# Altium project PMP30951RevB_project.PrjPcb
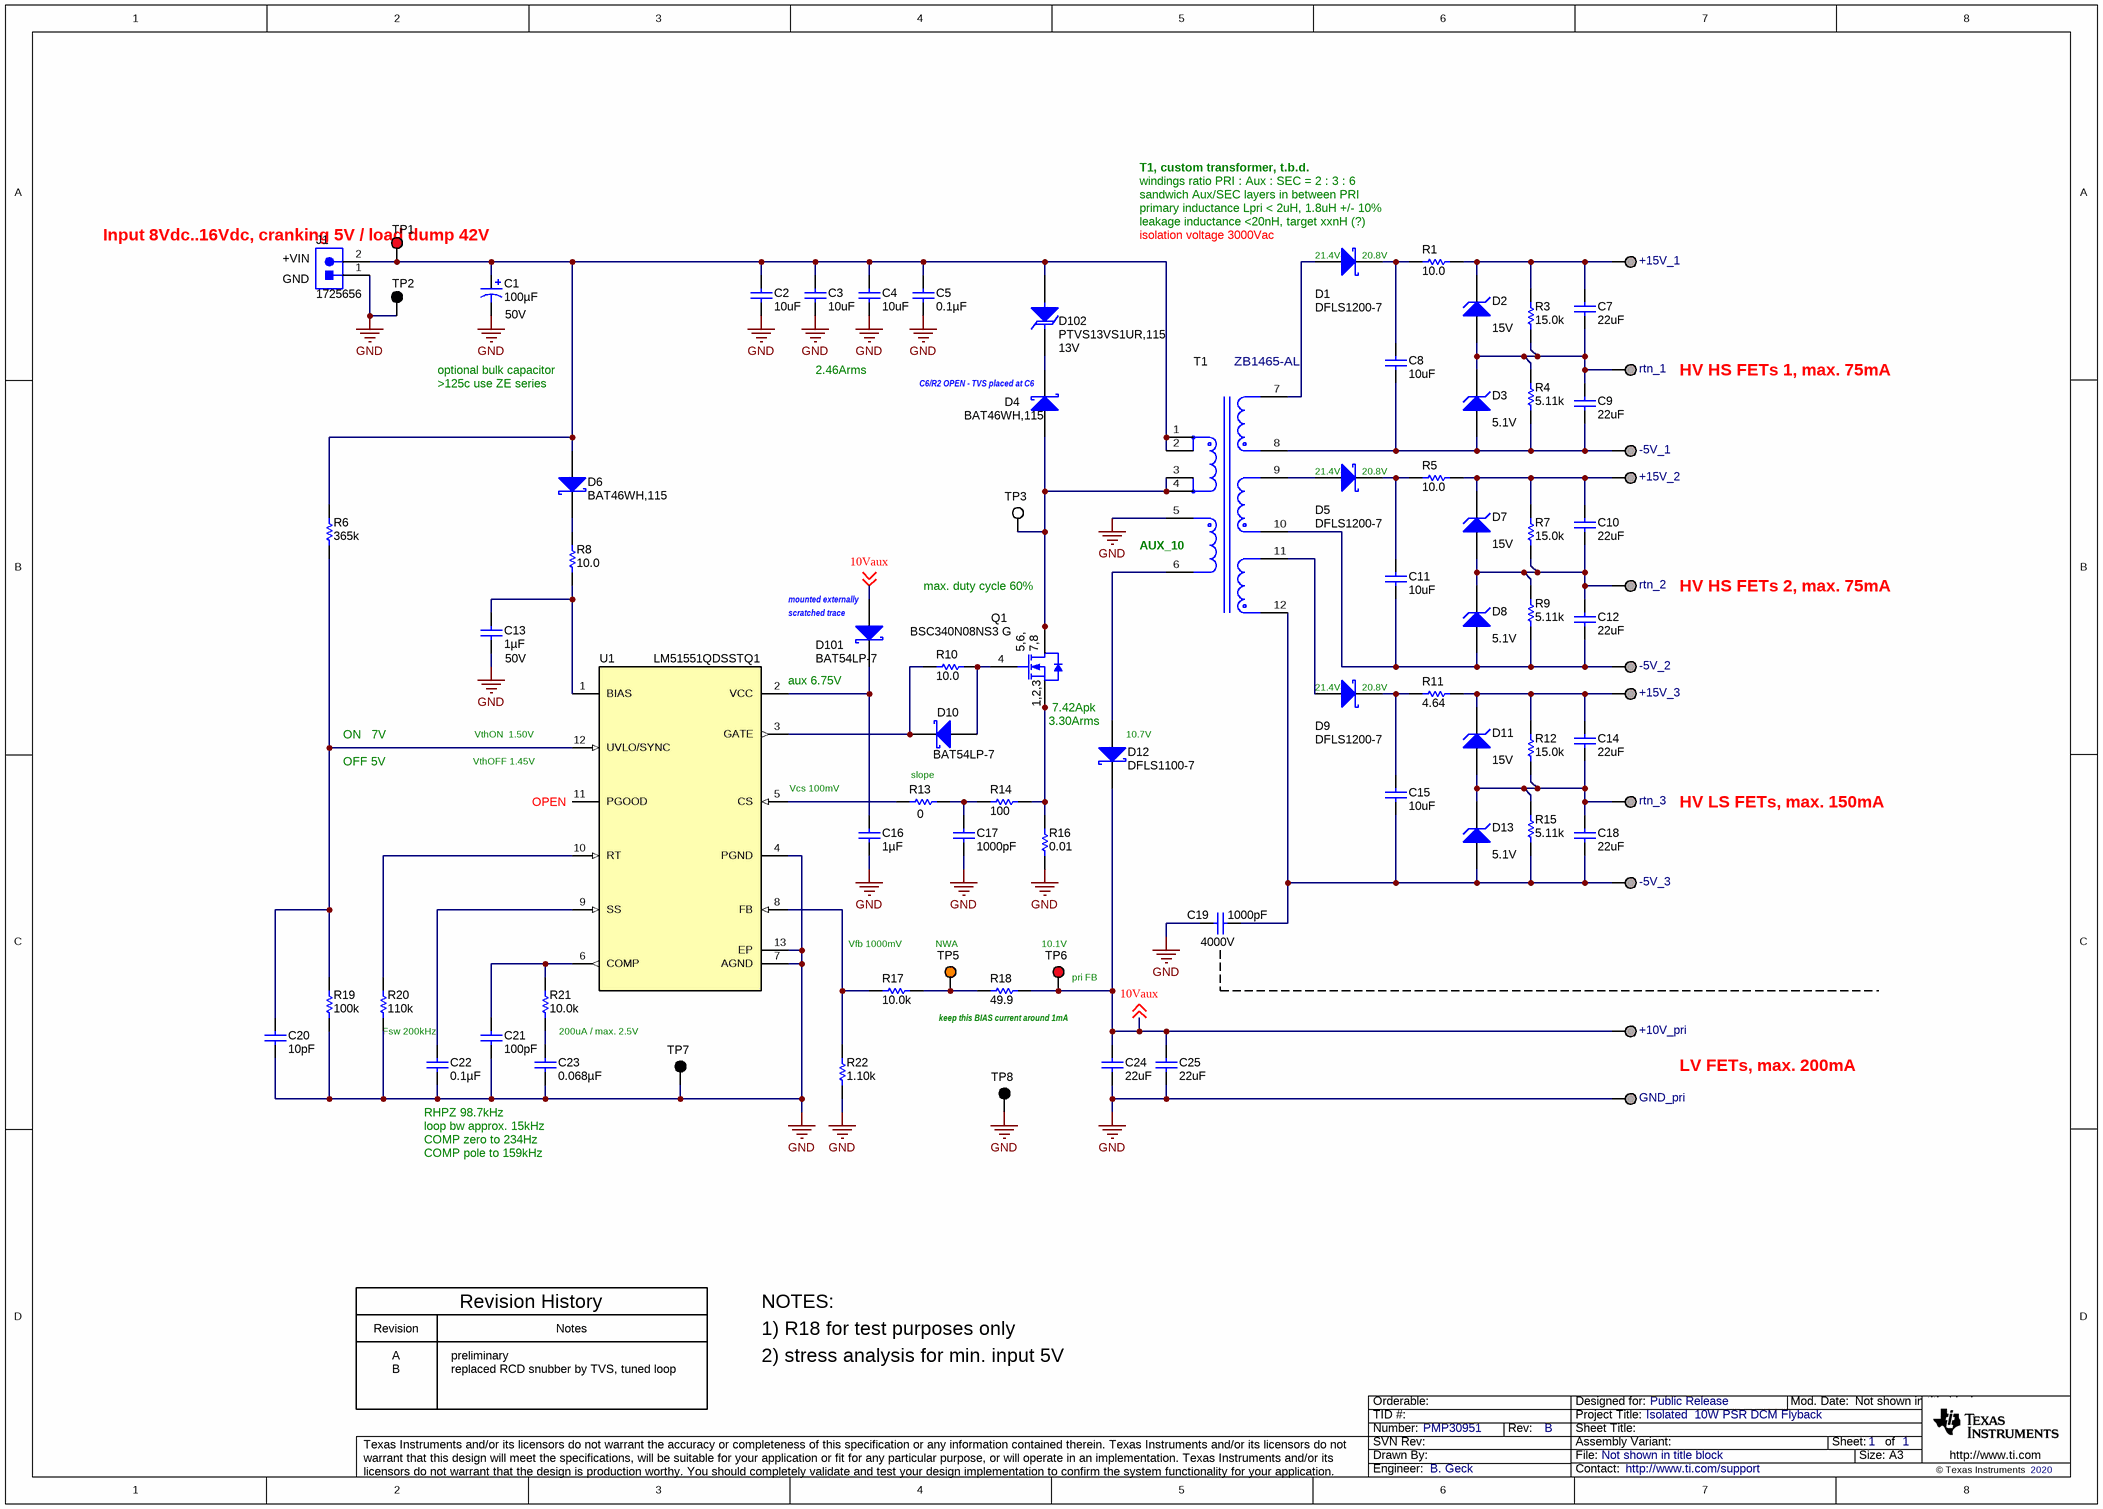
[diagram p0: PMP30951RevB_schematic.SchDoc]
TechSupport: http://www.ti.com/support; SCH_Rev: B; PRJ_Title: Isolated  10W PSR DCM Flyback; PRJ_Number: PMP30951; PRJ_Engineer: B. Geck; PRJ_Customer: Public Release; PCB_Rev: A1; PCB_Layout: B. Geck; CopyrightYear: 2020
1 sheet, 82 parts. Net scope: global (net labels, ports and power ports of the same name join across sheets).
Board file: PMP30951RevA1_board.PcbDoc

## Sheet PMP30951RevB_schematic.SchDoc
size A3; Date: Not shown in title block; ApprovedBy: Not shown in title block; CheckedBy: Not shown in title block; Author: Not shown in title block; CompanyName: Not shown in title block; Engineer: Not shown in title block; Organization: Not shown in title block; Address1: Not shown in title block; Address2: Not shown in title block; Address3: Not shown in title block; Address4: Not shown in title block; DocumentNumber: 1; Revision: Use project parameter SCH_Rev; SheetNumber: 1; SheetTotal: 1; PageSetup: Record=PageOptions¦CenterHorizontal=True¦CenterVertical=True¦PrintScale=0.68¦XCorrection=1.00¦YCorrection=1.00¦PrintKind=0¦BorderSize=5000000¦LeftOffset=0¦BottomOffset=0¦Orientation=2¦PaperLength=1000¦PaperWidth=1000¦Scale=100¦PaperSource=15¦PrintQuality=600¦MediaType=1¦DitherType=10¦PrintScaleMode=1¦PaperKind=A4¦PaperIndex=9

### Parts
+10V_pri  Suggest using a net name here  [Keystone1503-2]  (value not drawn)
+15V_1  Suggest using a net name here  [Keystone1503-2]  (value not drawn)
+15V_2  Suggest using a net name here  [Keystone1503-2]  (value not drawn)
+15V_3  Suggest using a net name here  [Keystone1503-2]  (value not drawn)
-5V_1  Suggest using a net name here  [Keystone1503-2]  (value not drawn)
-5V_2  Suggest using a net name here  [Keystone1503-2]  (value not drawn)
-5V_3  Suggest using a net name here  [Keystone1503-2]  (value not drawn)
C1  ValueDisplayed: 100µF  Value2: 50V  [Panasonic_G]  (hidden comment: EEH-ZC1H101P)
C2  ValueDisplayed: 10uF  [1210_270]  (hidden comment: GRM32ER71H106KA12L)
C3  ValueDisplayed: 10uF  [1210_270]  (hidden comment: GRM32ER71H106KA12L)
C4  ValueDisplayed: 10uF  [1210_270]  (hidden comment: GRM32ER71H106KA12L)
C5  ValueDisplayed: 0.1µF  [0603]  (hidden comment: GCM188R71H104KA57D)
C7  ValueDisplayed: 22uF  [1210_270]  (hidden comment: GRM32ER71E226KE15L)
C8  ValueDisplayed: 10uF  [1210_270]  (hidden comment: GRM32ER71H106KA12L)
C9  ValueDisplayed: 22uF  [1210_270]  (hidden comment: GRM32ER71E226KE15L)
C10  ValueDisplayed: 22uF  [1210_270]  (hidden comment: GRM32ER71E226KE15L)
C11  ValueDisplayed: 10uF  [1210_270]  (hidden comment: GRM32ER71H106KA12L)
C12  ValueDisplayed: 22uF  [1210_270]  (hidden comment: GRM32ER71E226KE15L)
C13  ValueDisplayed: 1µF  Value2: 50V  [0805_HV]  (hidden comment: GRM21BR71H105KA12L)
C14  ValueDisplayed: 22uF  [1210_270]  (hidden comment: GRM32ER71E226KE15L)
C15  ValueDisplayed: 10uF  [1210_270]  (hidden comment: GRM32ER71H106KA12L)
C16  ValueDisplayed: 1µF  [0603]  (hidden comment: GRM188R71C105KA12D)
C17  ValueDisplayed: 1000pF  [0603]  (hidden comment: GRM188R71E102KA01D)
C18  ValueDisplayed: 22uF  [1210_270]  (hidden comment: GRM32ER71E226KE15L)
C19  ValueDisplayed: 1000pF  Value2: 4000V  [1812_280]  (hidden comment: HV1812Y102KXVATHV)
C20  ValueDisplayed: 10pF  [0603]  (hidden comment: GRM1885C1H100JA01D)
C21  ValueDisplayed: 100pF  [0603]  (hidden comment: GRM1885C1H101JA01D)
C22  ValueDisplayed: 0.1µF  [0603]  (hidden comment: GRM188R71E104KA01D)
C23  ValueDisplayed: 0.068µF  [0603]  (hidden comment: GRM188R71E683KA01D)
C24  ValueDisplayed: 22uF  [1210_270]  (hidden comment: GRM32ER71E226KE15L)
C25  ValueDisplayed: 22uF  [1210_270]  (hidden comment: GRM32ER71E226KE15L)
D1  DFLS1200-7  [PowerDI123]
D2  value 15V  [SOD-123]  (hidden comment: MMSZ5245B-7-F)
D3  value 5.1V  [SOD-123]  (hidden comment: MMSZ5231B-7-F)
D4  BAT46WH,115  [SOD-123F]
D5  DFLS1200-7  [PowerDI123]
D6  BAT46WH,115  [SOD-123F]
D7  value 15V  [SOD-123]  (hidden comment: MMSZ5245B-7-F)
D8  value 5.1V  [SOD-123]  (hidden comment: MMSZ5231B-7-F)
D9  DFLS1200-7  [PowerDI123]
D10  BAT54LP-7  [X1-DFN1006-2]
D11  value 15V  [SOD-123]  (hidden comment: MMSZ5245B-7-F)
D12  DFLS1100-7  [PowerDI123]
D13  value 5.1V  [SOD-123]  (hidden comment: MMSZ5231B-7-F)
D101  BAT54LP-7  [X1-DFN1006-2]
D102  PTVS13VS1UR,115  value 13V  [SOD-123W]
GND_pri  Suggest using a net name here  [Keystone1503-2]  (value not drawn)
J1  1725656  [CONN_1725656]
Q1  BSC340N08NS3 G  [PG-TDSON-8]
R1  ValueDisplayed: 10.0  [0805_HV]  (hidden comment: CRCW080510R0FKEA)
R3  ValueDisplayed: 15.0k  [0603]  (hidden comment: CRCW060315K0FKEA)
R4  ValueDisplayed: 5.11k  [0603]  (hidden comment: CRCW06035K11FKEA)
R5  ValueDisplayed: 10.0  [0805_HV]  (hidden comment: CRCW080510R0FKEA)
R6  ValueDisplayed: 365k  [0603]  (hidden comment: CRCW0603365KFKEA)
R7  ValueDisplayed: 15.0k  [0603]  (hidden comment: CRCW060315K0FKEA)
R8  ValueDisplayed: 10.0  [0603]  (hidden comment: CRCW060310R0FKEA)
R9  ValueDisplayed: 5.11k  [0603]  (hidden comment: CRCW06035K11FKEA)
R10  ValueDisplayed: 10.0  [0603]  (hidden comment: CRCW060310R0FKEA)
R11  ValueDisplayed: 4.64  [0805_HV]  (hidden comment: CRCW08054R64FKEA)
R12  ValueDisplayed: 15.0k  [0603]  (hidden comment: CRCW060315K0FKEA)
R13  ValueDisplayed: 0  [0603]  (hidden comment: CRCW06030000Z0EA)
R14  ValueDisplayed: 100  [0603]  (hidden comment: CRCW0603100RFKEA)
R15  ValueDisplayed: 5.11k  [0603]  (hidden comment: CRCW06035K11FKEA)
R16  ValueDisplayed: 0.01  [WSLHP0805]  (hidden comment: WSL0805R0100FEA18)
R17  ValueDisplayed: 10.0k  [0603]  (hidden comment: CRCW060310K0FKEA)
R18  ValueDisplayed: 49.9  [0603]  (hidden comment: CRCW060349R9FKEA)
R19  ValueDisplayed: 100k  [0603]  (hidden comment: CRCW0603100KFKEA)
R20  ValueDisplayed: 110k  [0603]  (hidden comment: CRCW0603110KFKEA)
R21  ValueDisplayed: 10.0k  [0603]  (hidden comment: CRCW060310K0FKEA)
R22  ValueDisplayed: 1.10k  [0603]  (hidden comment: CRCW06031K10FKEA)
rtn_1  Suggest using a net name here  [Keystone1503-2]  (value not drawn)
rtn_2  Suggest using a net name here  [Keystone1503-2]  (value not drawn)
rtn_3  Suggest using a net name here  [Keystone1503-2]  (value not drawn)
T1  ZB1465-AL  [FP-ZB1465-AL_SMT_XFRMR_21MM97_17MM20-MFG]
TP1  5010  [Keystone5010]  (value not drawn)
TP2  5011  [Keystone5011]  (value not drawn)
TP3  5002  [Keystone5002]  (value not drawn)
TP5  5003  [Keystone5003]  (value not drawn)
TP6  5000  [Keystone5000]  (value not drawn)
TP7  5001  [Keystone5001]  (value not drawn)
TP8  5001  [Keystone5001]  (value not drawn)
U1  LM51551QDSSTQ1  [DSS0012C]

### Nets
GND: C1.2(-) C2.2 C3.2 C4.2 C5.2 C13.2 C16.2 C17.2 C19.2 C20.2 C21.2 C22.2 C23.2 C24.2 C25.2 GND_pri.1 J1.1 R16.1 R19.1 R20.1 R22.1 T1.5 TP2.1 TP7.1 TP8.1 U1.4(PGND) U1.7(AGND) U1.13(EP)
10Vaux: +10V_pri.1 C24.1 C25.1 D12.1(K) D101.2(A) R18.2 TP6.1 ; off-sheet 10Vaux
Net+15V_1_1: +15V_1.1 C7.1 D2.1(K) R1.2 R3.2
Net+15V_2_1: +15V_2.1 C10.1 D7.1(K) R5.2 R7.2
Net+15V_3_1: +15V_3.1 C14.1 D11.1(K) R11.2 R12.2
Net-5V_1_1: -5V_1.1 C8.2 C9.2 D3.2(A) R4.1 T1.8
Net-5V_2_1: -5V_2.1 C11.2 C12.2 D8.2(A) R9.1 T1.10
Net-5V_3_1: -5V_3.1 C15.2 C18.2 C19.1 D13.2(A) R15.1 T1.12
NetC1_1: C1.1(+) C2.1 C3.1 C4.1 C5.1 D6.2(A) D102.2(A) J1.2 R6.2 T1.1 T1.2 TP1.1
NetC7_2: C7.2 C9.1 D2.2(A) D3.1(K) R3.1 R4.2 rtn_1.1
NetC8_1: C8.1 D1.1(K) R1.1
NetC10_2: C10.2 C12.1 D7.2(A) D8.1(K) R7.1 R9.2 rtn_2.1
NetC11_1: C11.1 D5.1(K) R5.1
NetC13_1: C13.1 R8.1 U1.1(BIAS)
NetC14_2: C14.2 C18.1 D11.2(A) D13.1(K) R12.1 R15.2 rtn_3.1
NetC15_1: C15.1 D9.1(K) R11.1
NetC16_1: C16.1 D101.1(K) U1.2(VCC)
NetC17_1: C17.1 R13.2 R14.1
NetC20_1: C20.1 R6.1 R19.2 U1.12(UVLO/SYNC)
NetC21_1: C21.1 R21.2 U1.6(COMP)
NetC22_1: C22.1 U1.9(SS)
NetC23_1: C23.1 R21.1
NetD1_2: D1.2(A) T1.7
NetD4_1: D4.1(K) D102.1(K)
NetD4_2: D4.2(A) Q1.5(D) Q1.6(D) Q1.7(D) Q1.8(D) Q1.9(D) T1.3 T1.4 TP3.1
NetD5_2: D5.2(A) T1.9
NetD6_1: D6.1(K) R8.2
NetD9_2: D9.2(A) T1.11
NetD10_1: D10.1(K) R10.1 U1.3(GATE)
NetD10_2: D10.2(A) Q1.4(G) R10.2
NetD12_2: D12.2(A) T1.6
NetQ1_1: Q1.1(S) Q1.2(S) Q1.3(S) R14.2 R16.2
NetR13_1: R13.1 U1.5(CS)
NetR17_1: R17.1 R22.2 U1.8(FB)
NetR17_2: R17.2 R18.1 TP5.1
NetR20_2: R20.2 U1.10(RT)

Not connected (* = marked no-connect by the designer): U1 11(PGOOD)

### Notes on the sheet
- windings ratio PRI : Aux : SEC = 2 : 3 : 6
- T1, custom transformer, t.b.d.
- Input 8Vdc..16Vdc, cranking 5V / load dump 42V
- primary inductance Lpri < 2uH, 1.8uH +/- 10%
- leakage inductance <20nH, target xxnH (?)
- sandwich Aux/SEC layers in between PRI
- isolation voltage 3000Vac
- (near J1) +VIN
- (near J1) GND
- (near D1) 21.4V
- (near D1) 20.8V
- optional bulk capacitor
- >125c use ZE series
- 2.46Arms
- (near D4) C6/R2 OPEN - TVS placed at C6
- HV HS FETs 1, max. 75mA
- (near D5) 21.4V
- (near D5) 20.8V
- max. duty cycle 60%
- (near T1) AUX_10
- HV HS FETs 2, max. 75mA
- (near D101) scratched trace
- (near D101) mounted externally
- aux 6.75V
- 3.30Arms
- (near Q1) 7.42Apk
- (near D9) 21.4V
- (near D9) 20.8V
- ON   7V
- OFF 5V
- VthON  1.50V
- VthOFF 1.45V
- Vcs 100mV
- slope
- (near D12) 10.7V
- (near U1) OPEN
- HV LS FETs, max. 150mA
- Vfb 1000mV
- (near TP5) NWA
- (near TP6) 10.1V
- (near TP6) pri FB
- (near R20) Fsw 200kHz
- 200uA / max. 2.5V
- keep this BIAS current around 1mA
- (near C22) RHPZ 98.7kHz
- loop bw approx. 15kHz
- LV FETs, max. 200mA
- COMP zero to 234Hz
- COMP pole to 159kHz
- Revision
- Revision History
- Notes
- NOTES:
- 1) R18 for test purposes only
- A
- B
- preliminary
- replaced RCD snubber by TVS, tuned loop
- 2) stress analysis for min. input 5V

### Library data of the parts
+10V_pri +15V_1-+15V_3 -5V_1--5V_3 GND_pri rtn_1-rtn_3 = 1503-2: Terminal, Turret, TH, Double; Manufacturer: Keystone; CompType: Turret Terminal; U/M: EA
C1 = EEH-ZC1H101P: CAP, Polymer Hybrid, 100 µF, 50 V,+/- 20%, 0.028 ohm, AEC-Q200 Grade 1, D10xL10.2mm SMD; Manufacturer: Panasonic; Polarized: Y; CompType: Capacitor; Value: 100uF; U/M: EA; Cap_F: 0.0001; Tolerance_%: 20; VDC_V: 50; ESR_ohm: 0.028; IRMS_A: 1.6; TaMin_C: -55; TaMax_C: 125; Cap_Case: 10x10.2mm; SizeAreaWB_mm2: 151.29; SizeArea_mm2: 106.09; SizeX_mm: 10.3; SizeZ_mm: 10.5; AEC Category: Q200; AEC Grade: 1
C2-C4 C8 C11 C15 = CMP-0009226-3: CAP, CERM, 10 uF, 50 V, +/- 10%, X7R, 1210; Manufacturer: MuRata; Polarized: N; Value: 10uF; U/M: EA; Cap_F: 10µF; Value1: Unknown; VDC_V: 50V; TaMin_C: -55°C; TaMax_C: 125°C; Cap_Case: 1210; AEC Category: Q200; SizeArea_mm2: 8; SizeAreaWB_mm2: 14.7; SizeX_mm: 3.2; SizeY_mm: 2.5; SizeZ_mm: 2.7
C5 = GCM188R71H104KA57D: CAP, CERM, 0.1 µF, 50 V, +/- 10%, X7R, 0603; Manufacturer: MuRata; Polarized: N; CompType: Capacitor; Value: 0.1uF; U/M: EA; Cap_F: 0.0000001; Tolerance_%: 10; ESR_ohm: 0.02; Value1: 0.02 ohm; VDC_V: 50; Value2: 50V; IRMS_A: 1.84; TaMin_C: -55; TaMax_C: 125; AEC Category: Q200
C7 C9 C10 C12 C14 C18 C24 C25 = CMP-0009224-2: CAP, CERM, 22 uF, 25 V, +/- 10%, X7R, 1210; Manufacturer: MuRata; Polarized: N; Value: 22uF; U/M: EA; Cap_F: 22µF; Value1: Unknown; VDC_V: 25V; TaMin_C: -55°C; TaMax_C: 125°C; Cap_Case: 1210; AEC Category: Q200; SizeArea_mm2: 8; SizeAreaWB_mm2: 14.7; SizeX_mm: 3.2; SizeY_mm: 2.5; SizeZ_mm: 2.7
C13 = GRM21BR71H105KA12L: CAP, CERM, 1 µF, 50 V,+/- 10%, X7R, 0805; Manufacturer: MuRata; Polarized: N; CompType: Capacitor; Value: 1uF; U/M: EA; Cap_F: 0.000001; Tolerance_%: 10; VDC_V: 50; TaMin_C: -55; TaMax_C: 125; Cap_Case: 0805; SizeArea_mm2: 2.5; SizeAreaWB_mm2: 6.75; SizeX_mm: 2; SizeY_mm: 1.25; SizeZ_mm: 1.45; AEC Category: Q200; Green_Lifecycle: Active; Green_REACh: Passed
C16 = GRM188R71C105KA12D: CAP, CERM, 1 µF, 16 V, +/- 10%, X7R, 0603; Manufacturer: MuRata; Polarized: N; CompType: Capacitor; Value: 1uF; U/M: EA; Cap_F: 0.000001; Tolerance_%: 10; ESR_ohm: 0.011; Value1: 0.011 ohm; VDC_V: 16; Value2: 16V; TaMin_C: -55; TaMax_C: 125; AEC Category: Q200
C17 = GRM188R71E102KA01D: CAP, CERM, 1000 pF, 25 V,+/- 10%, X7R, 0603; Manufacturer: MuRata; Polarized: N; CompType: Capacitor; Value: 1000pF; U/M: EA; Cap_F: 0.000000001; Tolerance_%: 10; VDC_V: 25; Value2: 25V; TaMin_C: -55; TaMax_C: 125; SizeArea_mm2: 1.28; SizeAreaWB_mm2: 4.68; SizeX_mm: 1.6; SizeY_mm: 0.8; SizeZ_mm: 1; AEC Category: Q200; Green_Lifecycle: Active; Green_REACh: Passed
C19 = HV1812Y102KXVATHV: CAP, CERM, 1000 pF, 4000 V,+/- 10%, X7R, 1812; Manufacturer: Vishay-Vitramon; Polarized: N; CompType: Capacitor; Value: 1000pF; U/M: EA; Cap_F: 0.000000001; Tolerance_%: 10; VDC_V: 4000; TaMin_C: -55; TaMax_C: 125; Cap_Case: 1812; SizeArea_mm2: 14.4; SizeAreaWB_mm2: 23.1; SizeX_mm: 4.5; SizeY_mm: 3.2; SizeZ_mm: 2.8; AEC Category: Q200
C20 = GRM1885C1H100JA01D: CAP, CERM, 10 pF, 50 V,+/- 5%, C0G/NP0, 0603; Manufacturer: MuRata; Polarized: N; CompType: Capacitor; Value: 10pF; U/M: EA; Cap_F: 0.00000000001; Tolerance_%: 5; VDC_V: 50; Value2: 50V; TaMin_C: -55; TaMax_C: 125; SizeArea_mm2: 1.28; SizeAreaWB_mm2: 4.68; SizeX_mm: 1.6; SizeY_mm: 0.8; SizeZ_mm: 1; AEC Category: Q200; Green_Lifecycle: Active; Green_REACh: Passed
C21 = GRM1885C1H101JA01D: CAP, CERM, 100 pF, 50 V,+/- 5%, C0G/NP0, 0603; Manufacturer: MuRata; Polarized: N; CompType: Capacitor; Value: 100pF; U/M: EA; Cap_F: 0.0000000001; Tolerance_%: 5; VDC_V: 50; Value2: 50V; TaMin_C: -55; TaMax_C: 125; SizeArea_mm2: 1.28; SizeAreaWB_mm2: 4.68; SizeX_mm: 1.6; SizeY_mm: 0.8; SizeZ_mm: 1; AEC Category: Q200; Green_Lifecycle: Active; Green_REACh: Passed
C22 = GRM188R71E104KA01D: CAP, CERM, 0.1 µF, 25 V,+/- 10%, X7R, 0603; Manufacturer: MuRata; Polarized: N; CompType: Capacitor; Value: 0.1uF; U/M: EA; Cap_F: 0.0000001; Tolerance_%: 10; VDC_V: 25; Value2: 25V; TaMin_C: -55; TaMax_C: 125; SizeArea_mm2: 1.28; SizeAreaWB_mm2: 4.68; SizeX_mm: 1.6; SizeY_mm: 0.8; SizeZ_mm: 1; AEC Category: Q200; Green_Lifecycle: Active; Green_REACh: Passed
C23 = GRM188R71E683KA01D: CAP, CERM, 0.068 µF, 25 V,+/- 10%, X7R, 0603; Manufacturer: MuRata; Polarized: N; CompType: Capacitor; Value: 0.068uF; U/M: EA; Cap_F: 0.000000068; Tolerance_%: 10; VDC_V: 25; Value2: 25V; TaMin_C: -55; TaMax_C: 125; SizeArea_mm2: 1.28; SizeAreaWB_mm2: 4.68; SizeX_mm: 1.6; SizeY_mm: 0.8; SizeZ_mm: 1; AEC Category: Q200; Green_Lifecycle: Active; Green_REACh: Passed
D1 D5 D9 = DFLS1200-7: Diode, Schottky, 200 V, 1 A, PowerDI123; Manufacturer: Diodes Inc.; U/M: EA; Vf_V: 0.85; Value: 200V; Value1: 1A; Value2: 0.85V; Io_A: 1; Vr_V: 200; TJmax_C: 175; RJC_CperW: 7; SizeAreaWB_mm2: 13.066; SizeArea_mm2: 6.586; SizeX_mm: 3.7; SizeY_mm: 1.78; SizeZ_mm: 0.98; AEC Category: Q101; Green_Lifecycle: Active; Green_REACh: Passed
D2 D7 D11 = MMSZ5245B-7-F: Diode, Zener, 15 V, 500 mW, SOD-123; Manufacturer: Diodes Inc.; SymbolCreator: a0412235; U/M: EA; Power_W: 0.5; Vz_V: 15; Value1: 0.5W; RJA_CperW: 350; SizeAreaWB_mm2: 13.095; SizeArea_mm2: 6.545; SizeX_mm: 3.85; SizeY_mm: 1.7; SizeZ_mm: 1.35; AEC Category: Q101; Green_Lifecycle: Active; Green_REACh: Passed
D3 D8 D13 = MMSZ5231B-7-F: Diode, Zener, 5.1 V, 500 mW, SOD-123; Manufacturer: Diodes Inc.; SymbolCreator: a0412235; U/M: EA; Power_W: 0.5; Vz_V: 5.1; Value1: 0.5W; RJA_CperW: 350; SizeAreaWB_mm2: 13.095; SizeArea_mm2: 6.545; SizeX_mm: 3.85; SizeY_mm: 1.7; SizeZ_mm: 1.35; AEC Category: Q101; Green_Lifecycle: Active; Green_REACh: Passed
D4 D6 = BAT46WH,115: Diode, Schottky, 100 V, 0.25 A, SOD-123F; Manufacturer: Nexperia; U/M: EA; Vf_V: 0.85; Value: 100V; Value1: 0.25A; Value2: 0.85V; Io_A: 0.25; Vr_V: 100; TJmax_C: 150; SizeAreaWB_mm2: 11.7; SizeArea_mm2: 5.6; SizeX_mm: 3.5; SizeY_mm: 1.6; SizeZ_mm: 1.1; AEC Category: Q101; Green_Lifecycle: Not Set; Green_REACh: Incomplete
D10 D101 = BAT54LP-7: Diode, Schottky, 30 V, 0.2 A, 1.00x0.50x0.60mm; Manufacturer: Diodes Inc.; U/M: EA; Vf_V: 1; Value: 30V; Value1: 0.2A; Value2: 1V; Io_A: 0.2; Vr_V: 30; SizeAreaWB_mm2: 3.2; SizeArea_mm2: 0.6; SizeZ_mm: 0.53; AEC Category: Q101; Green_Lifecycle: Not Set; Green_REACh: Incomplete
D12 = DFLS1100-7: Diode, Schottky, 100 V, 1 A, PowerDI123; Manufacturer: Diodes Inc.; U/M: EA; Vf_V: 0.77; Value: 100V; Value1: 1A; Value2: 0.77V; Io_A: 1; Vr_V: 100; TJmax_C: 175; RJC_CperW: 7; SizeAreaWB_mm2: 13.066; SizeArea_mm2: 6.586; SizeX_mm: 3.7; SizeY_mm: 1.78; SizeZ_mm: 0.98; AEC Category: Q101; Green_Lifecycle: Active; Green_REACh: Passed
D102 = PTVS13VS1UR,115: Diode, TVS, Uni, 13 V, 21.5 Vc, SOD-123W; Manufacturer: Nexperia; U/M: EA; Vr_V: 13; Value1: W; RJA_CperW: 220; SizeAreaWB_mm2: 12.15; SizeArea_mm2: 5.95; SizeX_mm: 3.5; SizeY_mm: 1.7; SizeZ_mm: 1; AEC Category: Q101
J1 = 1725656: Terminal Block, 100mil, 2x1, 6A, 63V, TH; Manufacturer: Phoenix Contact; SymbolCreator: a0412235; Green_Lifecycle: Not Set; Green_REACh: Incomplete
Q1 = BSC340N08NS3 G: MOSFET, N-CH, 80 V, 23 A, PG-TDSON-8; Manufacturer: Infineon Technologies; Alternate Manufacturer: None; U/M: EA; ChType: N; Value: 80V; VdsMax_V: 80; Value1: 0.065 ohm; Rdson45_ohm: 0.065; Value2: 6.8 nC; QgTyp_nC: 6.8; Vgs_V: 20; IdsMax_A: 23; SizeAreaWB_mm2: 55.131; SizeArea_mm2: 29.351; SizeX_mm: 5.99; SizeY_mm: 4.9; SizeZ_mm: 1.12; AEC Category: Q101; Green_Lifecycle: Active; Green_REACh: Passed
R1 R5 = CRCW080510R0FKEA: RES, 10.0, 1%, 0.125 W, 0805; Manufacturer: Vishay-Dale; CompType: Resistor; Value: 10.0; Res_ohm: 10; Value_Code: 10R0; Tolerance_%: 1; Power_W: 0.125; Value2: 0.125W; VDC_V: 150; TempCo: 100 ppm/C; SizeArea_mm2: 2.5; SizeX_mm: 2; SizeY_mm: 1.25; SizeZ_mm: 1.45; EIA_Code: E96; U/M: EA; AEC Category: Q200; Green_Lifecycle: Active; Green_REACh: Passed
R3 R7 R12 = CRCW060315K0FKEA: RES, 15.0 k, 1%, 0.1 W, 0603; Manufacturer: Vishay-Dale; CompType: Resistor; Value: 15.0k; Res_ohm: 15000; Value_Code: 15k0; Tolerance_%: 1; Power_W: 0.1; Value2: 0.1W; VDC_V: 75; TempCo: 100 ppm/C; SizeArea_mm2: 1.28; SizeX_mm: 1.6; SizeY_mm: 0.8; EIA_Code: E96; U/M: EA; AEC Category: Q200; Green_Lifecycle: Active; Green_REACh: Passed
R4 R9 R15 = CRCW06035K11FKEA: RES, 5.11 k, 1%, 0.1 W, 0603; Manufacturer: Vishay-Dale; CompType: Resistor; Value: 5.11k; Res_ohm: 5110; Value_Code: 5k11; Tolerance_%: 1; Power_W: 0.1; Value2: 0.1W; VDC_V: 75; TempCo: 100 ppm/C; SizeArea_mm2: 1.28; SizeX_mm: 1.6; SizeY_mm: 0.8; EIA_Code: E96; U/M: EA; AEC Category: Q200; Green_Lifecycle: Active; Green_REACh: Passed
R6 = CRCW0603365KFKEA: RES, 365 k, 1%, 0.1 W, 0603; Manufacturer: Vishay-Dale; CompType: Resistor; Value: 365k; Res_ohm: 365000; Tolerance_%: 1; Power_W: 0.1; Value2: 0.1W; VDC_V: 75; TempCo: 100 ppm/C; SizeArea_mm2: 1.28; SizeX_mm: 1.6; SizeY_mm: 0.8; EIA_Code: E96; U/M: EA; AEC Category: Q200; Green_Lifecycle: Active; Green_REACh: Passed
R8 R10 = CRCW060310R0FKEA: RES, 10.0, 1%, 0.1 W, 0603; Manufacturer: Vishay-Dale; CompType: Resistor; Value: 10.0; Res_ohm: 10; Value_Code: 10R0; Tolerance_%: 1; Power_W: 0.1; Value2: 0.1W; VDC_V: 75; TempCo: 100 ppm/C; SizeArea_mm2: 1.28; SizeX_mm: 1.6; SizeY_mm: 0.8; EIA_Code: E96; U/M: EA; AEC Category: Q200; Green_Lifecycle: Active; Green_REACh: Passed
R11 = CRCW08054R64FKEA: RES, 4.64, 1%, 0.125 W, 0805; Manufacturer: Vishay-Dale; CompType: Resistor; Value: 4.64; Value_Code: 4R64; Tolerance_%: 1; Power_W: 0.125; Value2: 0.125W; VDC_V: 150; TempCo: 100 ppm/C; SizeArea_mm2: 2.5; SizeX_mm: 2; SizeY_mm: 1.25; SizeZ_mm: 1.45; EIA_Code: E96; U/M: EA; AEC Category: Q200
R13 = CRCW06030000Z0EA: RES, 0, 5%, 0.1 W, 0603; Manufacturer: Vishay-Dale; CompType: Resistor; Value: 0; Value_Code: 0000; Tolerance_%: 5; Power_W: 0.1; Value2: 0.1W; VDC_V: 75; TempCo: 200 ppm/C; SizeArea_mm2: 1.28; SizeX_mm: 1.6; SizeY_mm: 0.8; SizeZ_mm: 1; EIA_Code: E24; U/M: EA; AEC Category: Q200; Green_Lifecycle: Active; Green_REACh: Passed
R14 = CRCW0603100RFKEA: RES, 100, 1%, 0.1 W, 0603; Manufacturer: Vishay-Dale; CompType: Resistor; Value: 100; Value_Code: 100R; Tolerance_%: 1; Power_W: 0.1; Value2: 0.1W; VDC_V: 75; TempCo: 100 ppm/C; SizeArea_mm2: 1.28; SizeX_mm: 1.6; SizeY_mm: 0.8; EIA_Code: E96; U/M: EA; AEC Category: Q200; Green_Lifecycle: Active; Green_REACh: Passed
R16 = WSL0805R0100FEA18: RES, 0.01, 1%, 0.25 W, AEC-Q200 Grade 0, 0805; Manufacturer: Vishay-Dale; CompType: Resistor; Value: 0.01; Value_Code: R010; Tolerance_%: 1; Power_W: 0.25; Value2: 0.25W; TempCo: 75 ppm/C; SizeArea_mm2: 2.5781; SizeX_mm: 2.03; SizeY_mm: 1.27; SizeZ_mm: 0.51; EIA_Code: E96; U/M: EA; AEC Category: Q200; AEC Qualified: Y; AEC Grade: 0; Green_Lifecycle: Not Set; Green_REACh: Incomplete
R17 R21 = CRCW060310K0FKEA: RES, 10.0 k, 1%, 0.1 W, 0603; Manufacturer: Vishay-Dale; CompType: Resistor; Value: 10.0k; Res_ohm: 10000; Value_Code: 10k0; Tolerance_%: 1; Power_W: 0.1; Value2: 0.1W; VDC_V: 75; TempCo: 100 ppm/C; SizeArea_mm2: 1.28; SizeX_mm: 1.6; SizeY_mm: 0.8; EIA_Code: E96; U/M: EA; AEC Category: Q200; Green_Lifecycle: Active; Green_REACh: Passed
R18 = CRCW060349R9FKEA: RES, 49.9, 1%, 0.1 W, 0603; Manufacturer: Vishay-Dale; CompType: Resistor; Value: 49.9; Value_Code: 49R9; Tolerance_%: 1; Power_W: 0.1; Value2: 0.1W; VDC_V: 75; TempCo: 100 ppm/C; SizeArea_mm2: 1.28; SizeX_mm: 1.6; SizeY_mm: 0.8; EIA_Code: E96; U/M: EA; AEC Category: Q200
R19 = CRCW0603100KFKEA: RES, 100 k, 1%, 0.1 W, 0603; Manufacturer: Vishay-Dale; CompType: Resistor; Value: 100k; Res_ohm: 100000; Tolerance_%: 1; Power_W: 0.1; Value2: 0.1W; VDC_V: 75; TempCo: 100 ppm/C; SizeArea_mm2: 1.28; SizeX_mm: 1.6; SizeY_mm: 0.8; EIA_Code: E96; U/M: EA; AEC Category: Q200; Green_Lifecycle: Active; Green_REACh: Passed
R20 = CRCW0603110KFKEA: RES, 110 k, 1%, 0.1 W, 0603; Manufacturer: Vishay-Dale; CompType: Resistor; Value: 110k; Res_ohm: 110000; Tolerance_%: 1; Power_W: 0.1; Value2: 0.1W; VDC_V: 75; TempCo: 100 ppm/C; SizeArea_mm2: 1.28; SizeX_mm: 1.6; SizeY_mm: 0.8; EIA_Code: E96; U/M: EA; AEC Category: Q200; Green_Lifecycle: Active; Green_REACh: Passed
R22 = CRCW06031K10FKEA: RES, 1.10 k, 1%, 0.1 W, 0603; Manufacturer: Vishay-Dale; CompType: Resistor; Value: 1.10k; Res_ohm: 1100; Value_Code: 1k10; Tolerance_%: 1; Power_W: 0.1; Value2: 0.1W; VDC_V: 75; TempCo: 100 ppm/C; SizeArea_mm2: 1.28; SizeX_mm: 1.6; SizeY_mm: 0.8; EIA_Code: E96; U/M: EA; AEC Category: Q200; Green_Lifecycle: Active; Green_REACh: Passed
T1 = CMP-0091454-1: Flyback Transformer, 1.62uH, 1:1.5:3:3:3, VISO 3kVrms, 21.97x17.2x8.64mm; Manufacturer: Coilcraft; Ind_H: 1.62µH; AEC Qualified: No; SizeZ_mm: 8.64mm; Voltage_Isolation_Vrms: 3000Vrms
TP1 = CMP-0055147-1: Test Point, Multipurpose, Red, TH; Manufacturer: Keystone; CNHeader: FALSE; Green_Lifecycle: Active; Green_REACh: Passed; ContactFinish: Silver; CT: TRUE
TP2 = CMP-0055148-1: Test Point, Multipurpose, Black, TH; Manufacturer: Keystone; CNHeader: FALSE; Green_Lifecycle: Active; Green_REACh: Passed; ContactFinish: Silver; CT: TRUE
TP3 = 5002: Test Point, Miniature, White, TH; Manufacturer: Keystone; CompType: Test Point Loop; ContactFinish: Silver
TP5 = 5003: Test Point, Miniature, Orange, TH; Manufacturer: Keystone; CompType: Test Point Loop; ContactFinish: Silver
TP6 = 5000: Test Point, Miniature, Red, TH; Manufacturer: Keystone; CompType: Test Point Loop; U/M: EA
TP7 TP8 = 5001: Test Point, Miniature, Black, TH; Manufacturer: Keystone; CompType: Test Point Loop; U/M: EA
U1 = CMP-0081540-1: Automotive Grade 2.2-MHz Wide Input Non-synchronous Boost Controller, DSS0012C (WSON-12); Alternate PartNumber: LM51551QDSSRQ1; Alternate Manufacturer: Texas Instruments; SizeAreaWB_mm2: 12; SizeZ_mm: 0.8; SizeX_mm: 2; SizeY_mm: 3; SizeArea_mm2: 6; CompType: IC; AEC Qualified: Y; AEC Category: Q200

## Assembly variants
001: all parts fitted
